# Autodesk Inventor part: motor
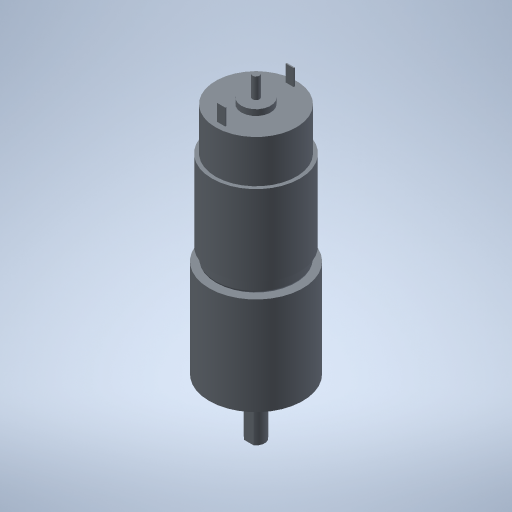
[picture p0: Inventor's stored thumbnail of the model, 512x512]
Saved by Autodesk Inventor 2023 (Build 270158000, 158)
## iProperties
Company: TraceParts S.A.
Created: 2021-03
Part Number: motor
Checked By: TraceParts S.A.
Material: Steel, Cast
Catalog Web Link: www.traceparts.com
Document SubType Name: Modeling
Designer: TraceParts
Density: 7.85 g/cm^3
Appearance: Semi-Polished
REFERENCE: PD3246-12-100-BF
DESIGN: Motors with gearbox, Nominal speed, 60 rpm
SUPPLIER: TRANSMOTEC
TraceParts.PartNumber: 90-15052019-026215
TraceParts.PartTitle: Planetary gear DC-motor-3246-BF
TraceParts.InstanceId: 90-15052019-0262152N3XX9WWY2MK673V115V3T3RA
TraceParts.PartStatus: Published
TraceParts.PartVersion: 1.0.3
TRACEPARTS: TRACEPARTS
TraceParts.PartLanguage: en
TraceParts.ClassPath: TRANSMOTEC_205044746:90-15052019-026215
Author: TraceParts
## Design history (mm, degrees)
feature "pd3246-12-100-bf"
body "Solid1"
